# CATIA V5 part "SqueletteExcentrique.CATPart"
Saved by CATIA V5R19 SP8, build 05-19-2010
Part number: SqueletteExcentrique
Bounding box of the stored display mesh (mm): x 0 to 20, y 91 to 100, z 60 to 60
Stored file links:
  C:\Users\rcousturie\Desktop\EU_thinkMotion\iao\IAO_MMS_Groupe1\abergami\abergami_catiaInitial\ObjetsInitials\SqueletteExcentrique.CATPart
  C:\Users\rcousturie\Desktop\EU_thinkMotion\iao\IAO_MMS_Groupe1\abergami\abergami_catiaInitial\ObjetsInitials\Product2.CATProduct
  C:\Users\rcousturie\Desktop\EU_thinkMotion\iao\IAO_MMS_Groupe1\abergami\abergami_catiaInitial\ObjetsInitials\Squelettebati.CATPart
  C:\Users\rcousturie\Desktop\EU_thinkMotion\iao\IAO_MMS_Groupe1\abergami\abergami_catiaInitial\ObjetsInitials\Squelettedebase.CATPart
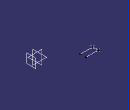
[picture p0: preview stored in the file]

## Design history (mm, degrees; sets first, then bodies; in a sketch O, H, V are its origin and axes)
Set1
  Point1: linked copy from another document
  Point2: linked copy from another document
Set2
  Line1: type Normal, RefPoint Point1, RefSkin yz-plane, Start 0, End 20
  Line2: type PtDir, RefPoint Point2, Direction yz-plane, Start 0, End 20
  Line3: type PtPt, FirstPoint Point2, SecondPoint Point1
  Plane1: type Offset, RefPlane yz-plane, Offset 10
Body1 (main body)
